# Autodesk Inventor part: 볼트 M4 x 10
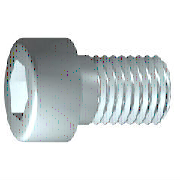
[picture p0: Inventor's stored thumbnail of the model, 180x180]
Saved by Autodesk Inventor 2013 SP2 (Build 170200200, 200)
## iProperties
IsCustomPart: 1
Created: 2012-02
Part Number: 볼트 M4 x 10
Material: 스테인리스강
Description: 6각 소켓 머리 캡 나사
Document SubType Name: Modeling
Standard: ISO 4762
Designer: mduedu
Standard Revision: Fourth edition 2004-03-01
Standards Organization: ISO
Language: ko-KR
Size Designation: M4 x 8
Categories: <MemberInstance><Categories><Category DisplayName="조임쇠" InternalName="e4da775c-781d-43d5-af7c-5136215cf5a6" Mnemonic="FSTN"><Category DisplayName="볼트" InternalN
Density: 7.75 g/cm^3
Author: mduedu
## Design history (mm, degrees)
sketch "스케치1"
  geometry: L1 (-1, 0)-(10, 0); L2 (10, 0)-(10, 2); L3 (10, 2)-(2.1, 2); L4 (2.1, 2)-(1.67, 2); L5 (1.67, 2)-(0, 2); L6 (0, 2)-(0, 3.5); L7 (0, 3.5)-(-4, 3.5); L8 (-4, 3.5)-(-4, 1.732); L9 (-4, 1.732)-(-2, 1.732); L10 (-2, 1.732)-(-1, 0); L11 (-6.8, 0)-(12.8, 0) reference; L12 (0, -0.7)-(0, 4.2) reference; L13 (2.1, 2)-(0, 2)
  constraints: 22 end point, 6 parallel, 2 collinear, 2 perpendicular, 1 horizontal, 1 point on line
  dimensions: "d1" = 7.9 distance from line of L3.end L2 (= GEL); "d2" = 0.42952 distance of L4.end L3.end (computed from GAL); "d3" = 4 distance between parallel lines of L8 L6 (= KOH); "d4" = 2 distance of L8.end L9.end (= INTI); "d5" = 60 deg angle of L10 L1; "d6" = 4 diameter of L3 L1 (= GD); "d7" = 4 diameter of L5 L1 (= BDM); "d8" = 3.4641 diameter of L9 L1 (= 1.1547 x SW); "d9" = 7 diameter of L7 L1 (= KOD); "d26" = 10 distance between parallel lines of L12 L2 (= NLG)
revolve "본체" sketch "스케치1" stored, may be unused: angle "d10" = 90 deg
sketch "스케치2"
  geometry: L1 (0, -4.9)-(0, 4.9) reference; L2 (-4.9, 0)-(4.9, 0) reference; L3 (1.732, 0)-(0.866, -1.5); L4 (0.866, -1.5)-(-0.866, -1.5); L5 (-0.866, -1.5)-(-1.732, 0); L6 (-1.732, 0)-(-0.866, 1.5); L7 (-0.866, 1.5)-(0.866, 1.5); L8 (0.866, 1.5)-(1.732, 0); 2 further points
  constraints: 12 end point, 1 coincident, 1 horizontal alignment, 1 point on line, 12 other
extrude "슬롯" join sketch "스케치2" stored distance "d11" = 10; taper "d12" = 0 deg
workplane "Work Plane1"
fillet "Fillet2" dims "d30" = 0.1 (= R)
body "Solid1"
fillet "모깎기1" dims "d17" = 0.4 (= RR)
feature "스레드" dims "d13" = 7.9 (= GEL), "d14" = 0
chamfer "모따기1" distance "d15" = 0.42941 (= -0.5 x SPD + 0.5 x GD); stored, may be unused: second distance "d16" = 0.42941 (= GUL), angle "d27" = 45 deg
other parameters: "GD" = 4 [user parameter; used in 2 equation terms], "NLG" = 10 [user parameter; used in 1 equation term], "GEL" = 7.9 [user parameter; used in 2 equation terms], "KOD" = 7 [user parameter; used in 1 equation term], "KOH" = 4 [user parameter; used in 1 equation term], "INTI" = 2 [user parameter; used in 1 equation term], "GAL" = 0.42941 (= 0.61345 x PTC) [user parameter; used in 1 equation term], "GUL" = 0.42941 (= 0.61345 x PTC) [user parameter; used in 1 equation term], "BDM" = 4 (= NND) [user parameter; used in 1 equation term], "SW" = 3 [user parameter; used in 2 equation terms], "RR" = 0.4 [user parameter; used in 1 equation term], "SPD" = 3.14117 (= NND - 1.2269 x PTC) [user parameter; used in 1 equation term], "d19" = 0, "d28" = 0, "d29" = 0, "R" = 0.1 [user parameter; used in 1 equation term], "TOA" = 30 deg [user parameter], "GD1" = 3.14117 (= THREADDIA - 1.2269 x PTC) [user parameter], "THREADDIA" = 4 [user parameter; used in 1 equation term], "FAWI" = 45 deg [user parameter], "TPU" = 14.28571 (computed from PTC) [user parameter], "PTC" = 0.7 [user parameter; used in 5 equation terms], "NND" = 4 [user parameter; used in 2 equation terms], "E0" = 3.465 (= 1.155 x SW) [user parameter]
